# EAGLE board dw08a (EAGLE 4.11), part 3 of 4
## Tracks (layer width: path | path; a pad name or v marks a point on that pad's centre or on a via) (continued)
I_DATA05  (via drill 0.61) (continued)
  Top 0.152: v51.44,4.51 32.51,23.43 30.86,23.43 B22.R2 | v130.18,31.3 131.44,32.58 v131.19,32.83 | v170.81,70.8 170.94,70.8 v175.26,66.48 202.82,38.92 203.07,38.92 226.82,15.18 227.46,15.18 v228.6,14.03 | v261.37,113.98 261.37,114.11 253.49,121.98 252.48,121.98 v241.94,132.52
  Bottom 0.152: v51.44,4.51 96.52,4.51 101.98,9.97 108.84,9.97 v130.18,31.3 | v131.19,32.83 131.83,32.83 146.94,47.94 147.96,47.94 v170.81,70.8 | v228.6,14.03 228.6,14.29 242.44,28.13 242.7,28.13 244.22,29.65 244.22,29.91 248.79,34.48 250.06,34.48 251.71,36.13 B05.L1 | v261.37,113.98 259.84,112.46 259.84,112.2 255.14,107.5 254,107.5 253.24,106.74 253.11,106.74 A05.L1 | v241.94,132.52 241.94,132.4 234.31,124.78 234.31,124.27 224.41,114.36 223.9,114.36 221.11,111.57 217.93,111.57 203.71,97.35 203.71,94.17 186.06,76.52 185.29,76.52 v175.26,66.48
I_DATA06  (via drill 0.61)
  Top 0.152: v263.02,42.48 263.02,46.55 258.19,51.37 v258.06,51.37 258.32,51.75 248.67,61.4 248.67,62.04 238.12,72.58 236.73,72.58 234.82,74.49 v233.04,74.49 | v277.88,73.98 279.02,73.98 279.91,74.87 279.91,77.28 267.21,89.98 267.21,93.15 265.56,94.81 265.3,94.81 263.78,96.33 263.78,96.58 259.21,101.16 257.94,101.16 256.29,102.81 A05.M1 | v101.47,7.81 89.41,7.81 88.01,9.21 78.99,9.21 78.23,9.97 61.47,9.97 17.78,53.66 17.78,54.8 B23.D2 | v126.75,12.26 v120.65,12.26 | v184.15,61.53 187.58,61.53 194.44,54.67 194.44,54.04 v203.58,44.9
  Bottom 0.152: v263.02,42.48 255.91,35.37 255.91,34.1 B05.M1 | v258.06,51.37 258.06,52.51 262.13,56.58 262.89,56.58 266.06,59.75 266.06,60.39 268.48,62.8 268.48,63.69 269.37,64.58 269.37,65.47 v277.88,73.98 | v101.47,7.81 107.82,7.81 112.27,12.26 v120.65,12.26 | v126.75,12.26 134.87,12.26 v184.15,61.53 | v203.58,44.9 205.23,44.9 221.74,61.4 221.74,64.58 223.39,66.23 223.77,66.23 229.62,72.07 230.63,72.07 v233.04,74.49
I_DATA07  (via drill 0.61)
  Top 0.152: v246.89,21.78 246.51,21.78 229.11,39.18 229.11,42.35 227.46,44.01 224.28,44.01 213.23,55.05 213.23,55.56 v211.71,57.09 | v224.66,70.67 224.66,73.22 v222.12,75.75 | v239.14,97.85 239.14,98.49 238.25,99.38 238.25,103.06 230.63,110.68 230.25,110.68 228.6,112.33 228.6,113.09 229.36,113.86 230.12,113.09 230.12,112.2 233.04,109.28 235.2,109.28 239.27,105.22 242.44,105.22 250.32,97.35 250.32,97.09 v251.33,96.08 | v132.84,136.08 138.56,136.08 185.29,89.34 187.2,89.34 187.45,89.09 190.12,89.09 v216.53,62.67
  Bottom 0.152: v246.89,21.78 247.27,22.16 248.67,22.16 253.11,26.61 254.89,26.61 B05.P1 | v211.71,57.09 211.71,57.72 216.66,62.67 | 216.66,62.67 v224.66,70.67 | v222.12,75.75 222.12,80.83 v239.14,97.85 | v251.33,96.08 254.51,96.08 254.89,96.46 A05.P1 | v132.84,136.08 110.62,113.86 93.22,113.86 34.42,55.05 34.42,51.88 32.89,50.35 23.37,50.35 22.61,49.59 18.16,49.59 B23.F2 | 216.66,62.67 v216.53,62.67
I_DATA08  (via drill 0.61)
  Top 0.152: v109.6,5.14 110.87,3.87 109.86,2.86 109.09,2.86 108.33,3.62 105.66,3.62 102.23,7.05 101.09,7.05 100.84,7.3 61.98,7.3 49.78,19.49 45.59,19.49 44.45,20.64 43.43,20.64 21.59,42.48 18.16,42.48 B23.J2 | v148.97,12.51 152.02,12.51 v154.56,9.97 | v206.38,52.77 206.88,52.77 214.88,44.77 | 214.88,44.77 247.78,11.87 v247.9,11.87 | v214.76,44.64 214.88,44.77
  Bottom 0.152: v109.6,5.14 141.6,5.14 v148.97,12.51 | v154.56,9.97 159.64,9.97 171.07,21.4 172.21,21.4 191.64,40.83 194.82,40.83 205.87,51.88 205.87,52.26 v206.38,52.77 | v247.9,11.87 248.41,11.87 253.49,16.95 253.49,18.1 255.27,19.88 B05.S1 | v214.76,44.64 216.41,46.29 216.41,46.55 235.08,65.22 235.08,65.72 235.71,66.36 235.71,67.25 236.6,68.14 236.6,70.04 240.54,73.98 240.66,73.98 247.14,80.45 247.14,80.58 247.65,81.09 247.78,81.09 250.32,83.63 250.32,83.76 251.33,84.77 251.46,84.77 255.27,88.58 255.27,89.72 A05.S1
I_DATA09  (via drill 0.61)
  Top 0.152: v67.44,67.69 v64.01,67.69 | v149.99,136.02 150.37,136.02 151,135.38 151.89,135.38 166.12,121.16 171.83,121.16 v187.71,105.28 | v195.58,111 195.58,110.74 216.92,89.41 217.17,89.41 v218.19,88.39 | v217.17,87.25 217.68,87.25 220.98,83.95 221.36,83.95 v233.43,71.88 | v230.89,67.06 231.65,67.06 241.68,57.02 241.68,56.52 v242.82,55.37 | v230.89,139.06 235.46,134.49 235.46,134.37 235.59,134.37 235.59,134.24 235.71,134.24 235.71,134.11 235.84,134.11 235.84,133.99 235.97,133.99 235.97,133.86 236.09,133.86 238.63,131.32 238.63,131.19 238.76,131.19 238.76,131.06 238.89,131.06 238.89,130.94 239.01,130.94 239.01,130.81 239.14,130.81 239.14,130.68 239.27,130.68 241.81,128.14 241.81,128.02 241.94,128.02 241.94,127.89 242.06,127.89 242.06,127.76 242.19,127.76 242.19,127.64 242.32,127.64 242.32,127.51 242.44,127.51 242.57,127.38 243.08,127.38 244.6,125.86 245.36,125.86 A05.D2 | v223.52,131.95 222.12,131.95 v219.33,134.75
  Bottom 0.152: v64.01,67.69 63.63,67.31 63.63,66.8 34.42,37.59 23.24,37.59 22.61,36.96 18.16,36.96 B23.L2 | v67.44,67.69 67.44,68.07 70.99,71.63 71.37,71.63 75.06,75.31 75.06,76.71 93.09,94.74 96.39,94.74 107.44,105.79 107.44,108.97 108.46,109.98 108.46,110.11 108.58,110.11 108.58,110.24 108.71,110.24 108.71,110.36 108.84,110.36 108.84,110.49 108.97,110.49 108.97,110.62 114.81,110.62 115.19,111 115.7,111 140.72,136.02 v149.99,136.02 | v187.71,105.28 189.87,105.28 v195.58,111 195.58,111.38 218.95,134.75 v219.33,134.75 | v218.19,88.39 218.19,88.27 v217.17,87.25 | v233.43,71.88 233.43,69.6 v230.89,67.06 | v242.82,55.37 245.36,55.37 B05.D2 | v230.89,139.06 230.63,139.06 v223.52,131.95
I_DATA10  (via drill 0.61)
  Top 0.152: v193.29,141.41 196.34,141.41 199.26,138.49 199.26,138.37 202.06,135.57 202.56,135.57 v212.09,126.05 | v229.62,139.13 229.62,139 232.54,136.08 233.3,136.08 242.32,127.06 242.82,127.06 245.62,124.27 246.89,124.27 248.54,122.62 A05.E2 | v238.12,40.07 238.12,39.69 v247.65,30.16 | v225.04,11.62 223.9,11.62 v207.77,27.75 | v183.9,3.87 178.69,3.87 163.96,18.61 160.78,18.61 152.91,26.48 152.91,30.04 150.11,32.83 150.11,34.61 138.43,46.29 138.43,46.8 136.65,48.58 136.65,50.35 136.4,50.61 136.4,52.51 133.22,55.69 133.22,56.2 124.97,64.45 124.97,64.96 v119,70.93
  Bottom 0.152: v193.29,141.41 187.32,136.08 185.29,136.08 158.62,109.41 158.12,109.41 140.97,92.27 140.59,92.27 135.64,87.31 135.38,87.31 v119,70.93 99.69,51.63 99.44,51.63 95.25,47.43 95.25,46.93 66.93,18.61 61.47,18.61 58.29,15.43 45.59,15.43 42.42,12.26 36.07,12.26 34.92,11.11 32.26,13.78 32.26,14.8 33.4,15.94 19.56,29.78 18.16,29.78 B23.N2 | v212.09,126.05 213.36,126.05 213.87,126.56 217.04,126.56 v229.62,139.13 | v238.12,40.07 238.63,40.58 238.63,43.37 247.27,52.01 248.54,52.01 B05.E2 | v247.65,30.16 230.63,13.14 227.71,13.14 227.2,12.64 226.06,12.64 v225.04,11.62 | v183.9,3.87 v207.77,27.75
I_DATA11  (via drill 0.61)
  Top 0.152: v162.94,91.5 162.94,91.38 178.94,75.37 178.94,74.74 191.9,61.78 191.9,61.02 193.55,59.37 193.55,59.12 217.93,34.73 218.69,34.73 v229.11,24.32 | v254.38,118.68 249.68,123.38 249.3,123.38 v247.78,124.9 | v249.81,126.94 249.17,126.94 v239.4,136.72 | v231.39,123.76 v229.62,125.54 | v226.19,117.54 225.68,117.54 225.3,117.92 225.04,117.92 223.39,119.57 223.01,119.57 219.2,123.38 219.2,123.89 214.88,128.21 214.88,128.71 214.25,129.35 212.85,129.35 211.84,130.37 211.2,130.37 209.8,131.76 209.55,131.76 208.41,132.91 206.5,132.91 v205.99,133.41
  Bottom 0.152: v229.11,24.32 231.27,26.48 231.27,29.65 242.44,40.83 242.95,40.83 243.46,41.34 243.46,41.85 245.62,44.01 246.89,44.01 248.54,45.66 B05.H2 | B23.R2 17.78,23.05 17.78,18.86 20.7,15.94 19.56,14.8 19.56,13.78 22.23,11.11 23.37,12.26 33.27,12.26 41.4,4.13 49.91,4.13 51.05,5.27 58.42,5.27 61.98,8.83 76.58,8.83 150.24,82.49 152.53,82.49 152.91,82.87 154.31,82.87 v162.94,91.5 163.32,91.76 174.5,102.93 175.64,102.93 184.53,111.82 184.53,112.46 185.55,113.47 185.55,114.11 202.18,130.75 203.58,130.75 205.99,133.16 v205.99,133.41 | v254.38,118.68 251.97,116.27 249.94,116.27 A05.H2 | v249.81,126.94 v247.78,124.9 | v239.4,136.72 236.22,136.72 231.9,132.4 231.9,131.25 230.5,129.86 229.87,129.86 229.11,129.09 229.11,128.46 228.35,127.7 228.35,126.81 v229.62,125.54 | v231.39,123.76 231.39,121.86 227.46,117.92 226.57,117.92 v226.19,117.54
I_DATAIN  (via drill 0.61)
  Top 0.152: v87.63,22.16 92.08,22.16 v107.95,6.29 | v214,96.33 214,97.6 v213.74,97.85 | v228.22,114.75 228.22,120.46 v225.68,123 | v247.4,136.84 248.92,136.84 259.84,125.92 259.84,122.75 262,120.59 v262.13,120.59 | v255.02,113.6 263.65,104.97 263.65,104.2 262.76,103.31 262.64,103.44 A04.M2 | v263.27,31.94 262.51,32.7 262.38,32.7 B04.M2 | v305.69,82.49 305.69,83.25 305.31,83.63 305.31,87.06 300.36,92.01 300.36,92.52 298.2,94.68 298.2,96.71 297.81,97.09 297.81,97.73 300.86,100.78 279.91,121.73 279.91,124.9 v274.32,130.49
  Bottom 0.152: v87.63,22.16 87.5,22.04 86.11,23.43 81.66,23.43 B18.R2 | v107.95,6.29 131.7,6.29 147.19,21.78 151,21.78 187.96,58.74 187.96,59.37 189.99,61.4 189.99,68.14 190.63,68.77 190.63,71.94 198.25,79.57 198.25,80.07 200.03,81.85 200.03,82.87 207.14,89.98 207.65,89.98 v214,96.33 | v213.74,97.85 214.38,97.85 219.2,102.68 219.46,102.68 219.84,103.06 219.84,103.44 225.3,108.9 225.3,109.41 228.09,112.2 228.09,114.62 v228.22,114.75 | v225.68,123 226.31,123 227.33,124.02 227.58,124.02 227.97,124.4 229.74,124.4 235.97,130.62 236.47,130.62 242.32,136.46 247.01,136.46 v247.4,136.84 | v255.02,113.6 262,120.59 v262.13,120.59 262.51,120.84 272.16,130.49 v274.32,130.49 | v263.27,31.94 263.27,32.58 263.91,33.21 263.91,33.34 264.29,33.72 264.8,33.72 276.86,45.78 276.86,46.67 282.07,51.88 282.07,56.83 288.42,63.18 288.67,63.18 292.99,67.5 292.99,70.93 295.4,73.34 295.4,74.74 304.04,83.38 304.8,83.38 v305.69,82.49
I_EXTA0  (via drill 0.61)
  Top 0.152: v106.05,4.38 101.6,8.83 98.04,8.83 96.9,9.97 93.22,9.97 84.45,18.73 83.44,18.73 82.68,19.49 70.99,19.49 68.58,21.91 68.58,23.05 B19.R2 | v215.14,68.64 218.44,68.64 220.34,70.55 v227.2,63.69 | v234.06,1.46 228.85,1.46 v224.41,5.91 | v214.88,1.46 214.38,0.95 208.53,0.95 202.18,7.3 201.8,7.3 189.23,19.88 188.98,19.88 v173.23,35.62
  Bottom 0.152: v106.05,4.38 141.99,4.38 v173.23,35.62 178.82,41.21 179.32,41.21 201.17,63.06 205.23,63.06 205.99,63.82 207.77,63.82 210.57,66.61 213.11,66.61 v215.14,68.64 | v227.2,63.69 229.74,66.23 232.03,66.23 246,80.2 A05.V2 | v234.06,1.46 241.05,8.45 241.68,8.45 243.59,10.35 244.22,10.35 244.6,10.73 245.36,10.73 B05.V2 | v224.41,5.91 221.62,5.91 218.69,2.98 216.41,2.98 v214.88,1.46
I_EXTA1  (via drill 0.61)
  Top 0.152: v248.28,16.45 247.65,17.08 246.76,17.08 B05.T2 | v262.76,30.29 262.76,30.92 260.86,32.83 260.86,36.01 252.86,44.01 252.48,44.01 v251.59,44.9 | v263.91,68.64 266.57,68.64 270,72.07 269.49,72.58 269.49,74.49 269.24,74.74 269.24,74.99 266.06,78.17 259.71,78.17 v247.65,90.23 247.4,90.61 243.84,94.17 v243.84,94.68 | v95.63,11.75 87.88,19.49 83.69,19.49 73.41,29.78 68.96,29.78 B19.N2 | v172.59,76.01 176.02,76.01 177.8,74.23 178.18,74.23 189.99,62.42 189.99,62.04 v190.75,61.28 | v194.06,63.06 197.61,63.06 v201.42,59.24
  Bottom 0.152: v248.28,16.45 248.92,16.45 v262.76,30.29 | v251.59,44.9 251.59,46.8 256.67,51.88 256.67,53.91 254.51,56.07 256.67,58.23 256.67,61.4 258.32,63.06 258.7,63.06 259.59,63.94 259.59,64.33 v263.91,68.64 | v247.65,90.23 247.65,89.34 246.38,88.08 A05.T2 | v95.63,11.75 99.06,11.75 99.57,12.26 103.89,12.26 157.99,66.36 162.94,66.36 v172.59,76.01 | v190.75,61.28 192.28,61.28 v194.06,63.06 | v201.42,59.24 203.71,59.24 210.69,66.23 213.87,66.23 230.5,82.87 232.03,82.87 v243.84,94.68
I_EXTA2  (via drill 0.61)
  Top 0.152: v253.87,13.65 249.56,17.97 249.56,19.88 B05.S2 | v244.35,3.62 236.09,3.62 227.46,12.26 225.55,12.26 225.43,12.38 224.16,12.38 208.53,28 208.53,28.13 207.65,29.02 207.52,29.02 206.88,29.65 206.88,33.59 v206.76,33.72 | v216.03,44.77 216.03,45.78 v214.25,47.56 | v109.47,3.62 93.6,19.49 90.04,19.49 88.14,21.4 87.25,21.4 76.45,32.19 70.99,32.19 68.58,34.61 68.58,35.75 B19.L2 | v169.42,9.08 172.34,9.08 v175.01,6.41
  Bottom 0.152: v253.87,13.65 253.37,13.65 251.33,11.62 251.33,10.6 v244.35,3.62 | v216.03,44.77 215.39,44.13 215.39,42.35 v206.76,33.72 206.5,33.34 201.29,28.13 197.99,28.13 195.45,25.59 194.82,25.59 189.1,19.88 188.47,19.88 v175.01,6.41 | v214.25,47.56 224.92,58.23 224.92,62.67 225.55,63.31 225.55,65.22 247.14,86.81 247.14,87.95 248.92,89.72 A05.S2 | v109.47,3.62 146.69,3.62 148.21,5.14 165.48,5.14 v169.42,9.08
I_INIT  (via drill 0.61)
  Top 0.152: v275.21,93.53 v292.35,76.39 | B01.V2 296.16,10.73 292.74,10.73 283.34,1.33 279.4,1.33 275.08,5.65 266.7,5.65 264.8,7.56 264.16,7.56 261.62,10.1 260.1,10.1 259.46,10.73 B04.V2 258.44,11.87 256.67,13.65 256.67,14.8 251.59,19.88 251.59,20.77 242.57,29.78 240.41,29.78 B06.N1 239.4,30.92 237.62,32.7 237.62,33.85 232.92,38.54 232.92,39.56 227.84,44.64 v227.84,46.93
  Bottom 0.152: v275.21,93.53 263.02,81.34 259.46,81.34 A04.V2 258.44,80.2 258.44,76.39 257.3,75.25 257.3,74.99 254,71.69 253.62,71.69 251.33,69.41 251.08,69.41 250.82,69.15 250.44,69.15 250.32,69.03 249.94,69.03 v227.84,46.93 | v292.35,76.39 292.48,76.39 296.42,80.33 A01.V2
I_IOP1  (via drill 0.61)
  Top 0.152: v309.88,52.77 309.88,85.53 306.07,89.34 305.94,89.34 305.31,89.98 305.31,91 306.58,92.27 305.44,93.41 304.67,93.41 303.28,92.01 302.13,93.15 302.13,104.33 v300.36,106.11 | v248.03,60.26 247.14,61.15 247.14,62.42 244.86,64.71 243.59,64.71 B06.A1 | v260.6,72.83 260.6,74.23 264.16,77.79 265.3,77.79 v265.68,77.41
  Bottom 0.152: v309.88,52.77 303.4,46.29 303.4,45.78 300.36,42.74 300.36,40.45 B01.K2 | v300.36,106.11 300.36,108.78 A01.K2 299.34,109.16 297.69,107.5 296.29,107.5 266.19,77.41 v265.68,77.41 | v248.03,60.26 v260.6,72.83
I_IOP2  (via drill 0.61)
  Top 0.152: v270.89,85.15 v275.72,80.33 | v294.64,29.53 294.51,29.53 281.31,42.74 280.92,42.74 269.11,54.55 269.11,55.18 v254.89,69.41
  Bottom 0.152: 255.02,69.28 v270.89,85.15 | 255.02,69.28 245.36,59.63 245.11,59.63 243.97,58.48 243.97,58.23 241.68,55.94 240.41,55.94 B06.D1 | v275.72,80.33 275.72,80.45 283.72,88.46 283.97,88.46 285.62,90.11 285.62,90.36 296.42,101.16 297.69,101.16 299.34,102.81 A01.M2 | v294.64,29.53 298.07,32.96 299.34,32.96 B01.M2 | 255.02,69.28 v254.89,69.41
I_IOP4  (via drill 0.61)
  Top 0.152: v264.16,25.97 263.02,27.11 263.02,27.5 241.68,48.83 240.41,48.83 B06.F1 | B01.P2 299.34,27.37 297.94,28.77 294.26,28.77 281.05,41.97 v280.92,41.97 280.67,42.35 268.22,54.8 v268.22,54.93 | v301.12,92.39 300.36,93.15 300.36,96.08 A01.P2
  Bottom 0.152: v264.16,25.97 264.92,25.97 v280.92,41.97 | v301.12,92.39 301.12,89.85 300.99,89.72 300.99,87.82 291.34,78.17 290.7,78.17 271.02,58.48 271.02,57.72 v268.22,54.93
I_IRQ  (via drill 0.61)
  Top 0.152: v274.32,30.35 274.32,32.64 B03.M2 | v243.46,4.45 236.35,4.45 v236.09,4.7 | v229.87,3.43 227.97,3.43 224.66,6.73 221.74,6.73 219.07,9.4 216.66,9.4 216.15,9.91 212.6,9.91 v207.14,15.37 | v195.45,7.11 194.94,7.11 191.77,10.29 191.39,10.29 189.48,12.19 185.17,12.19 181.23,16.13 179.2,16.13 176.78,18.54 173.61,18.54 v173.48,18.67 | v161.04,6.99 146.56,6.99 143.89,9.65 143.76,9.65 143.76,9.78 143.64,9.78 143.64,9.91 143.51,9.91 143.51,10.03 143.38,10.03 143.38,10.16 143.26,10.16 143.26,10.29 140.59,10.29 135.51,15.37 132.33,15.37 131.7,16 130.43,16 122.94,23.5 121.03,23.5 119.63,24.89 109.47,24.89 101.6,32.77 101.09,32.77 85.47,48.39 82.04,48.39 81.66,48.77 B18.F2 | v230.89,142.88 233.17,142.88 235.33,140.72 237.87,140.72 238.25,140.34 239.65,140.34 267.21,112.78 267.21,108.97 272.54,103.63 273.94,103.63 A03.M2 | v215.9,128.4 215.77,128.4 214.5,129.67 213.11,129.67 v204.6,138.18 | v194.18,133.86 191.26,133.86 189.23,135.89 186.94,135.89 v184.28,138.56 | v97.28,87.25 97.28,85.34 v101.6,81.03
  Bottom 0.152: v274.32,30.35 273.81,30.35 265.81,22.35 265.3,22.35 259.33,16.38 254.89,16.38 248.03,9.53 248.03,9.02 v243.46,4.45 | v236.09,4.7 232.28,4.7 231.01,3.43 v229.87,3.43 | v207.14,15.37 203.71,15.37 v195.45,7.11 | v173.48,18.67 172.72,18.67 v161.04,6.99 | v230.89,142.88 229.87,142.88 229.24,142.24 228.6,142.24 220.73,134.37 220.73,133.48 216.41,129.16 216.41,128.91 v215.9,128.4 | v204.6,138.18 202.95,138.18 201.55,136.78 201.55,136.4 199.01,133.86 v194.18,133.86 | v184.28,138.56 166.62,138.56 164.21,136.14 153.54,136.14 135.64,118.24 134.24,118.24 119.89,103.89 118.24,103.89 116.46,102.11 112.14,102.11 v97.28,87.25 | v101.6,81.03 101.6,72.01 99.06,69.47 98.81,69.47 98.55,69.22 98.17,69.22 98.04,69.09 97.79,69.09 97.66,68.96 92.46,68.96 91.69,68.2 91.69,62.1 84.84,55.24 84.84,54.74 83.06,52.96 83.06,51.56 81.41,49.91 B18.F2
I_LINE  (via drill 0.61)
  Top 0.152: v94.49,47.31 99.82,47.31 105.79,41.34 106.3,41.34 131.32,16.32 137.67,16.32 144.02,9.97 147.07,9.97 v149.22,7.81 | v171.45,20.64 172.59,19.49 178.44,19.49 181.99,15.94 187.83,15.94 v200.15,3.62 | v214.12,8.45 214.88,8.45 v220.98,2.35 | v237.49,17.72 237.87,17.72 245.62,9.97 249.94,9.97 252.73,7.18 258.83,7.18 v261.87,4.13 | v288.8,62.42 287.27,63.94 286.77,63.94 271.78,78.93 271.78,80.2 A03.V2 | v283.72,53.28 283.72,53.15 289.05,47.82 289.05,46.67 v297.94,37.78
  Bottom 0.152: v94.49,47.31 84.07,36.89 81.66,36.89 B18.L2 | v149.22,7.81 158.62,7.81 v171.45,20.64 | v200.15,3.62 209.3,3.62 v214.12,8.45 | v220.98,2.35 222.12,2.35 v237.49,17.72 | v261.87,4.13 264.16,4.13 270.76,10.73 B03.V2 272.16,11.49 273.81,13.14 275.08,13.14 297.94,36.01 v297.94,37.78 | v288.8,62.42 288.8,58.36 v283.72,53.28
I_MB00  (via drill 0.61)
  Top 0.152: v241.3,109.54 249.17,101.66 249.17,101.16 252.09,98.23 252.09,97.98 262.25,87.82 263.02,87.82 271.4,79.44 271.4,78.68 288.42,61.66 289.81,61.66 B02.B1 | v253.11,121.09 252.73,121.09 246,127.83 245.24,127.83 243.33,129.73 242.57,129.73 240.41,131.89 A06.B1 | v284.1,133.41 285.37,132.14 289.81,132.14 A02.B1
  Bottom 0.152: A07.H2 224.16,116.65 224.16,117.79 236.09,129.73 237.36,129.73 239.01,131.38 A06.B1 | v241.3,109.54 251.97,120.21 252.22,120.21 v253.11,121.09 256.03,121.09 268.35,133.41 v284.1,133.41
I_MB01  (via drill 0.61)
  Top 0.152: v241.17,122.87 241.17,123.51 240.03,124.65 A06.D1 | 262.64,85.92 261.87,86.68 261.87,87.19 251.84,97.22 251.46,97.22 242.7,105.98 242.19,105.98 v239.9,108.27 | 262.64,85.92 270.89,77.66 271.4,77.66 290.19,58.86 290.19,56.33 B02.D1 | v225.93,96.08 225.93,96.33 224.28,97.98 223.01,97.98 221.36,99.63 A07.N2 | v292.1,115.63 282.07,125.67 284.23,127.83 284.99,127.83 287.02,125.79 289.81,125.79 A02.D1 | 262.64,85.92 v262.51,85.79
  Bottom 0.152: v241.17,122.87 220.98,102.68 220.98,100.78 A07.N2 | v239.9,108.27 238.12,108.27 v225.93,96.08 | v292.1,115.63 291.85,115.63 264.03,87.82 264.03,87.31 v262.51,85.79
I_MB02  (via drill 0.61)
  Top 0.152: v226.19,82.87 225.3,83.76 224.54,83.76 A07.U2 | v235.59,92.27 235.59,93.92 226.44,103.06 226.44,104.2 v213.74,116.9 | v219.96,123.76 221.74,123.76 224.41,126.43 236.09,114.75 239.4,114.75 v239.65,114.49 | v244.73,120.08 244.6,120.08 243.21,121.47 A06.E1 | v238.51,111.06 262.51,87.06 | 262.51,87.06 293.37,56.2 293.37,53.15 B02.E1 | v293.75,119.44 293.75,121.47 A02.E1 | 262.51,87.06 v262.64,87.06
  Bottom 0.152: v226.19,82.87 226.19,83.38 233.17,90.36 233.68,90.36 v235.59,92.27 | v213.74,116.9 215.39,118.56 215.39,120.08 215.77,120.46 216.66,120.46 216.92,120.71 217.55,120.71 218.57,121.73 218.57,122.36 v219.96,123.76 | v244.73,120.08 239.65,115 v239.65,114.49 239.4,114.11 238.51,113.22 v238.51,111.06 | v293.75,119.44 293.75,118.43 291.34,116.01 291.34,115.76 v262.64,87.06
I_MB03  (via drill 0.61)
  Top 0.152: v229.62,117.79 230.89,117.79 236.09,112.58 236.85,112.58 238.12,113.86 239.01,112.97 A06.J1 240.41,112.33 242.06,110.68 243.33,110.68 261.11,92.9 | v291.85,45.53 291.85,46.29 286.26,51.88 286.26,53.15 285.62,53.78 285.62,55.69 284.61,56.71 284.35,56.71 282.32,58.74 282.32,58.99 275.08,66.23 274.83,66.23 273.3,67.75 273.3,70.04 v270.26,73.09 | v273.69,78.3 273.69,80.33 261.11,92.9 | v286.13,117.03 287.78,117.03 289.05,115.76 289.05,115.25 290.19,114.11 290.19,113.47 A02.J1 | 261.11,92.9 v262,92.9
  Bottom 0.152: v229.62,117.79 213.61,101.79 211.46,101.79 210.06,100.39 208.66,100.39 A08.N2 | v291.85,45.53 290.83,44.51 290.83,43.62 B02.J1 | v270.26,73.09 270.26,74.87 v273.69,78.3 | v262,92.9 v286.13,117.03
I_MB03\  (via drill 0.61)
  Top 0.152: v224.41,125.28 225.04,125.28 v236.35,113.98 | 239.9,116.14 242.19,116.14 A06.H1 | v239.01,116.14 239.9,116.14 | v242.7,41.72 248.28,36.13 248.28,35.62 249.43,34.48 249.68,34.48 258.83,25.34 259.33,25.34 280.54,4.13 281.31,4.13 283.46,1.97 302.01,20.51 302.01,29.02 301.12,29.91 301.12,33.85 299.59,35.37 299.59,37.15 299.08,37.66 299.08,38.29 294,43.37 294,45.28 B02.H1 | v246.63,46.93 248.28,48.58 246.51,50.35 246.13,50.35 244.6,51.88 244.6,52.39 242.06,54.93 242.06,55.56 v240.92,56.71 | v244.35,62.17 244.22,62.17 235.71,70.67 235.71,70.8 233.81,72.71 233.17,72.71 221.62,84.26 221.23,84.26 209.93,95.57 208.53,95.57 v202.18,101.92 | v273.18,100.01 273.05,100.01 265.56,107.5 v263.52,107.5 | v257.18,103.19 256.03,104.33 251.71,104.33 239.9,116.14
  Bottom 0.152: 215.26,116.14 211.84,116.14 A08.H2 | 215.26,116.14 v224.41,125.28 | v236.35,113.98 236.85,113.98 v239.01,116.14 | v242.7,41.72 242.7,42.99 v246.63,46.93 | v240.92,56.71 240.92,58.36 242.44,59.88 243.08,59.88 243.59,60.39 243.59,61.4 v244.35,62.17 | v202.18,101.92 202.18,102.17 210.69,110.68 210.95,110.68 211.84,111.57 211.84,112.71 215.26,116.14 | v273.18,100.01 294.39,121.22 295.15,120.46 295.15,119.7 294.77,119.32 294.77,118.94 294,118.17 294,116.65 A02.H1 | v263.52,107.5 261.49,107.5 v257.18,103.19
I_MB04  (via drill 0.61)
  Top 0.152: v230,94.3 229.87,94.3 v206.38,117.79 | v200.79,114.36 200.28,114.36 199.14,115.51 A09.H2 | v264.54,64.83 266.19,63.18 266.32,63.18 293.37,36.13 293.37,34.1 B02.M1 | v287.4,87.82 287.4,87.95 285.37,89.98 | 285.37,89.98 v284.86,90.49 | v242.06,101.28 242.06,100.27 251.46,90.87 252.48,90.87 v257.81,85.53 | v273.18,98.74 274.83,98.74 281.05,92.52 281.05,92.01 282.07,91 282.07,89.72 283.21,88.58 283.97,88.58 285.37,89.98
  Bottom 0.152: v230,94.3 238.51,102.81 242.19,102.81 A06.M1 242.57,102.42 242.57,101.79 v242.06,101.28 | v206.38,117.79 205.61,117.79 204.85,117.03 204.34,117.03 202.06,114.75 201.17,114.75 v200.79,114.36 | v264.54,64.83 264.54,65.47 286.51,87.44 287.02,87.44 v287.4,87.82 | v284.86,90.49 284.86,91.89 289.05,96.08 289.05,96.97 291.59,99.5 291.59,100.65 293.37,102.42 A02.M1 | v257.81,85.53 258.57,85.53 267.97,94.93 269.37,94.93 v273.18,98.74
I_MB04\  (via drill 0.61)
  Top 0.152: v213.11,82.23 211.71,83.63 A08.U2 | v285.12,32.7 284.48,32.7 261.75,55.44 261.75,56.45 v251.33,66.86 | v223.52,92.52 223.52,92.39 228.09,87.82 228.09,87.31 230.12,85.28 230.63,85.28 234.44,81.47 234.44,81.09 v248.79,66.74
  Bottom 0.152: v213.11,82.23 214.5,83.63 214.76,83.63 223.52,92.39 | 223.52,92.39 232.66,101.54 233.17,101.54 235.97,104.33 237.36,104.33 239.01,105.98 A06.L1 | v285.12,32.7 288.54,36.13 289.81,36.13 B02.L1 | A02.L1 289.81,105.98 289.43,105.6 288.54,105.6 287.27,104.33 286.89,104.33 275.97,93.41 275.97,93.15 274.45,91.63 274.19,91.63 257.68,75.12 257.68,74.87 251.33,68.52 v251.33,66.86 250.95,66.74 v248.79,66.74 | 223.52,92.39 v223.52,92.52
I_MB05  (via drill 0.61)
  Top 0.152: v299.59,28.64 299.59,30.42 268.35,61.66 268.35,62.17 v266.57,63.94 258.7,71.82 258.7,72.45 250.95,80.2 250.95,84.01 246.51,88.46 245.24,88.46 243.59,90.11 A06.S1 242.57,91.25 240.79,93.03 240.79,94.17 229.24,105.73 v228.6,105.73 | v203.58,82.61 202.44,83.76 199.14,83.76 A09.U2
  Bottom 0.152: v299.59,28.64 294,23.05 294,21.4 B02.S1 | v203.58,82.61 204.85,81.34 205.61,82.11 205.61,82.74 v228.6,105.73 | v266.57,63.94 267.21,64.58 267.21,65.6 284.61,83 287.78,83 291.59,86.81 291.59,87.06 293.37,88.84 293.37,89.72 A02.S1
I_MB05\  (via drill 0.61)
  Top 0.152: v197.61,98.49 196.47,99.63 195.96,99.63 A09.N2 | v211.07,111.95 211.71,111.95 219.84,103.82 219.84,103.31 v233.55,89.6 | v230.5,86.04 246.89,69.66 247.01,69.66 v257.56,59.12 292.74,23.94 293.24,23.94 293.75,24.45 293.75,26.23 B02.P1
  Bottom 0.152: v197.61,98.49 v211.07,111.95 | A06.P1 242.19,96.46 240.54,94.81 239.27,94.81 234.06,89.6 v233.55,89.6 233.3,89.22 230.5,86.42 v230.5,86.04 | v257.56,59.12 293.37,94.93 293.37,96.08 A02.P1
I_MB06  (via drill 0.61)
  Top 0.152: v199.9,87.82 199.52,88.2 197.61,88.2 190.63,95.19 190.63,95.44 186.44,99.63 183.26,99.63 A10.N2 | v285.37,50.35 285.37,50.48 282.96,52.9 282.96,54.67 v271.78,65.85 | v278.76,74.87 278.76,76.14 266.06,88.84 266.06,89.85 265.94,89.98 265.94,91.25 v257.18,100.01 | v254.38,136.08 256.03,136.08 272.54,119.57 272.54,118.3 v273.3,117.54
  Bottom 0.152: v199.9,87.82 199.9,88.46 201.42,89.98 202.06,89.98 207.26,95.19 207.52,95.19 227.84,115.51 228.22,115.51 229.74,117.03 230,117.03 230.38,117.41 230.38,117.67 232.92,120.21 234.44,120.21 235.97,121.73 A06.E2 237.24,122.62 238.76,122.62 240.54,124.4 241.3,124.4 245.11,128.21 246.51,128.21 v254.38,136.08 | v285.37,50.35 286.77,51.75 286.89,51.75 B02.E2 | v271.78,65.85 271.78,66.99 273.69,68.9 273.94,68.9 278.64,73.6 278.64,74.74 v278.76,74.87 | v257.18,100.01 264.67,107.5 269.62,107.5 273.3,111.19 | 273.3,111.19 277.88,115.76 278.51,115.76 283.97,121.22 286,121.22 286.64,121.86 A02.E2 | v273.3,117.54 273.3,111.19
I_MB06\  (via drill 0.61)
  Top 0.152: v201.29,123.38 v209.93,123.38 | v221.87,129.86 225.17,129.86 227.97,127.06 230.63,127.06 232.66,125.03 A06.D2 233.68,124.65 233.68,121.6 v234.19,121.09 | A10.H2 v188.47,115.89 | v282.96,60.39 v284.86,58.48 | v294.51,79.69 294.51,81.72 288.16,88.08 288.16,88.2 287.02,89.34 286.89,89.34 286.26,89.98 286.26,90.23 285.24,91.25 284.99,91.25 279.91,96.33 279.91,100.52 v269.11,111.32
  Bottom 0.152: v188.47,115.89 190.5,115.89 194.82,120.21 198.12,120.21 v201.29,123.38 | v209.93,123.38 214.12,123.38 214.63,123.89 215.9,123.89 v221.87,129.86 | v284.86,58.48 284.48,58.1 284.48,56.33 B02.D2 | v282.96,60.39 282.96,64.45 285.37,66.86 285.37,67.63 285.75,68.01 285.75,69.28 287.02,70.55 287.02,72.2 v294.51,79.69 | v269.11,111.32 269.11,115 271.78,117.67 272.29,117.67 272.92,118.3 275.46,118.3 280.54,123.38 281.81,123.38 283.46,125.03 A02.D2 284.73,125.92 286.26,127.44 286.26,129.09 287.91,130.75 281.81,136.84 254,136.84 245.75,128.59 244.98,128.59 242.95,126.56 239.27,126.56 234.19,121.47 v234.19,121.09
I_MB07  (via drill 0.61)
  Top 0.152: v270.26,58.1 271.65,56.71 271.91,56.71 287.02,41.59 287.02,40.45 B02.K2 | v290.96,78.93 290.45,78.93 276.35,93.03 276.35,94.3 v275.97,94.68 | v288.67,107.63 288.67,107.76 287.65,108.78 A02.K2 | v177.8,120.21 178.69,120.21 v212.09,86.81 | v264.54,96.71 v270.89,90.36 | v257.3,90.61 257.3,91.25 251.71,96.84 251.33,96.84 242.57,105.6 242.06,105.6 240.16,107.5 238.89,107.5 237.24,109.16 A06.K2
  Bottom 0.152: v270.26,58.1 270.26,58.23 v290.96,78.93 | v288.67,107.63 275.97,94.93 v275.97,94.68 275.59,94.42 274.95,94.42 v270.89,90.36 | v177.8,120.21 175.77,120.21 173.35,117.79 173.35,116.65 A11.H2 | v212.09,86.81 212.09,87.19 220.6,95.69 221.11,95.69 232.92,107.5 234.19,107.5 235.84,109.16 A06.K2 | v264.54,96.71 263.4,96.71 v257.3,90.61
I_MB07\  (via drill 0.61)
  Top 0.152: v187.32,81.09 186.06,82.36 186.06,83.38 A10.U2 | v221.11,114.62 v227.97,107.76 228.22,107.38 251.33,84.26 251.33,84.01 | 251.33,84.01 251.33,80.33 259.08,72.58 259.08,71.94 264.67,66.36 266.06,66.36 267.21,65.22 267.21,64.58 268.99,62.8 269.49,62.8 270.38,61.91 270.38,61.4 282.7,49.09 282.7,48.58 284.86,46.42 286.64,46.42 B02.H2 | 251.33,84.01 v251.71,84.01
  Bottom 0.152: v187.32,81.09 187.32,81.47 217.81,111.95 218.31,111.95 220.98,114.62 v221.11,114.62 | v227.97,107.76 230,107.76 234.44,112.2 234.44,113.35 236.22,115.13 A06.H2 | v251.71,84.01 251.84,84.01 259.97,92.14 262.38,92.14 264.03,93.79 264.03,94.17 285.37,115.51 286.64,115.51 A02.H2
I_MB08  (via drill 0.61)
  Top 0.152: v174.88,82.11 173.48,83.5 A11.U2 | v194.94,102.17 195.71,102.17 208.28,89.6 208.28,88.58 212.22,84.64 212.22,84.39 214.5,82.11 216.41,82.11 v218.31,80.2 | v261.49,50.23 277.62,34.1 277.62,33.59 283.85,27.37 286.64,27.37 B02.P2 | 245.36,58.86 243.97,60.26 243.97,60.77 237.24,67.5 236.73,67.5 v221.11,83.12 | 245.36,58.86 v257.68,46.55 | v282.96,95.31 v285.24,95.31 | 245.36,58.86 v245.49,58.86
  Bottom 0.152: v174.88,82.11 v194.94,102.17 | 221.23,83.12 232.92,94.81 234.19,94.81 235.84,96.46 A06.P2 | v218.31,80.2 221.23,83.12 | v261.49,50.23 261.37,50.23 v257.68,46.55 | 221.23,83.12 v221.11,83.12 | v285.24,95.31 286.38,96.46 286.64,96.46 A02.P2 | v282.96,95.31 282.96,94.68 277.11,88.84 276.61,88.84 271.78,84.01 270.38,84.01 261.49,75.12 261.49,74.87 v245.49,58.86
I_MB08\  (via drill 0.61)
  Top 0.152: v171.7,97.98 170.31,99.38 A11.N2 | v185.67,111.95 186.44,111.95 208.66,89.72 208.66,89.09 v214.88,82.87 | v292.99,24.83 292.86,24.83 287.65,30.04 287.65,32.58 B02.M2 | v277.37,13.14 273.05,13.14 v232.92,53.28 | v244.73,72.96 244.22,72.96 240.28,76.9 240.28,77.53 v225.04,92.77 | v288.93,104.84 288.93,105.73 281.69,112.97 281.69,113.6 279.91,115.38 279.91,118.05 279.65,118.3 279.65,119.7 270.64,128.71 269.75,128.71 v264.54,133.92 | v231.14,106.87 231.27,106.87 232.92,105.22 234.19,105.22 235.84,103.57 A06.M2
  Bottom 0.152: v171.7,97.98 v185.67,111.95 | v214.88,82.87 214.88,83.12 223.39,91.63 223.77,91.63 224.28,92.14 224.28,92.52 224.79,93.03 | 224.79,93.03 232.92,101.16 233.3,101.16 234.7,102.55 235.59,102.55 235.84,102.81 A06.M2 | v292.99,24.83 292.99,24.7 287.78,19.49 283.72,19.49 v277.37,13.14 | v232.92,53.28 232.92,53.53 240.79,61.4 240.79,69.03 v244.73,72.96 | 224.79,93.03 v225.04,92.77 | v288.93,104.84 287.91,103.82 287.91,103.69 A02.M2 | v264.54,133.92 263.14,133.92 262.51,133.29 257.94,133.29 248.28,123.64 247.14,123.64 243.97,120.46 243.97,119.95 238.89,114.87 238.89,114.62 236.73,112.46 236.73,112.08 232.03,107.38 231.65,107.38 v231.14,106.87
I_MB09  (via drill 0.61)
  Top 0.152: v163.32,116.27 163.7,116.27 175.51,104.46 175.64,104.46 179.83,100.27 179.83,100.14 v188.59,91.38 | v211.71,113.73 211.71,113.09 219.96,104.84 220.6,104.84 232.92,92.52 234.19,92.52 235.84,90.87 A06.S2 236.85,89.72 238.63,87.95 238.63,86.81 241.05,84.39 v241.05,77.28 | 259.21,51.37 255.78,54.8 255.78,55.44 238.25,72.96 237.62,72.96 v237.24,73.34 | 259.21,51.37 287.02,23.56 287.02,21.4 B02.S2 | v285.75,88.46 285.75,87.31 v290.07,83 | 259.21,51.37 v259.33,51.37
  Bottom 0.152: v163.32,116.27 161.04,116.27 A12.H2 | v188.59,91.38 189.36,91.38 200.28,102.3 200.41,102.3 210.31,112.2 210.31,112.33 v211.71,113.73 | v237.24,73.34 237.24,73.47 v241.05,77.28 | v285.75,88.46 287.02,89.72 A02.S2 | v290.07,83 290.07,82.11 289.43,81.47 289.43,81.22 286.38,78.17 286.13,78.17 270.38,62.42 270.38,62.17 269.49,61.28 269.24,61.28 v259.33,51.37
I_MB10  (via drill 0.61)
  Top 0.152: B02.T2 284.86,17.84 286.26,17.84 289.69,21.27 289.69,23.05 289.43,23.3 289.43,26.48 262.38,53.53 258.19,53.53 v256.54,55.18 229.11,82.61 v228.98,82.61 228.73,83 214.5,97.22 214.5,98.23 212.47,100.27 211.46,100.27 195.33,116.39 v194.31,116.39 | v165.1,106.36 165.48,106.36 v173.35,98.49 | v285.88,85.15 284.48,86.55 A02.T2
  Bottom 0.152: v228.98,82.61 228.98,84.52 229.74,85.28 231.01,85.28 232.66,86.93 A06.T2 | v165.1,106.36 159.13,100.39 157.86,100.39 A12.N2 | v173.35,98.49 173.35,98.74 178.94,104.33 182.12,104.33 189.99,112.2 189.99,112.58 191.01,113.6 191.52,113.6 v194.31,116.39 | v285.88,85.15 285.88,84.77 266.83,65.72 266.83,65.47 v256.54,55.18
I_MB11  (via drill 0.61)
  Top 0.152: v269.11,62.04 282.32,48.83 282.32,48.45 300.36,30.42 300.36,30.16 301.62,28.89 301.62,26.86 286.26,11.49 284.86,11.49 B02.V2 | v286,78.93 284.61,80.33 A02.V2 | v240.92,73.22 233.81,80.33 A06.V2 | v247.9,80.2 248.79,80.2 249.68,79.31 249.68,78.93 263.02,65.6 263.02,64.71 263.91,63.82 264.8,63.82 266.19,62.42 266.19,62.17 v267.59,60.77 | v178.31,68.26 162.81,83.76 161.04,83.76 A12.U2 | v185.8,75.63 186.06,75.63 v192.79,68.9 | v215.52,85.79 217.42,85.79 220.34,82.87 220.34,82.74 220.98,82.11 221.11,82.11 227.71,75.5 v227.71,75.37
  Bottom 0.152: v286,78.93 v269.11,62.04 268.73,61.78 267.72,60.77 v267.59,60.77 | v240.92,73.22 v247.9,80.2 | v178.31,68.26 178.44,68.26 v185.8,75.63 | v192.79,68.9 200.15,68.9 203.96,72.71 203.96,74.23 v215.52,85.79 | v227.71,75.37 232.79,80.45 A06.V2
I_MBINCR  (via drill 0.61)
  Top 0.152: 235.46,41.21 235.46,42.35 233.81,44.01 233.17,44.01 231.65,45.53 231.65,46.16 230.63,47.18 230.25,47.18 v228.6,48.83 | 235.46,41.21 235.46,39.18 256.79,17.84 258.06,17.84 B04.T2 | v148.59,4.38 143,9.97 131.32,9.97 122.17,19.11 115.32,19.11 114.94,19.49 109.09,19.49 85.34,43.24 82.68,43.24 70.74,55.18 68.96,55.18 B19.D2 | v174.62,9.08 179.96,9.08 v186.06,2.98 | v233.68,41.21 235.46,41.21
  Bottom 0.152: v228.6,48.83 228.6,49.21 231.27,51.88 231.27,53.66 229.36,55.56 234.95,61.15 234.95,61.91 237.62,64.58 237.62,66.99 237.74,67.12 237.74,68.39 239.4,70.04 240.03,70.04 247.52,77.53 248.67,77.53 249.68,78.55 249.68,79.82 255.14,85.28 256.41,85.28 258.06,86.93 A04.T2 | v148.59,4.38 169.93,4.38 v174.62,9.08 | v186.06,2.98 197.1,2.98 201.42,7.3 201.68,7.3 209.8,15.43 209.8,17.21 228.47,35.88 228.47,36.39 231.27,39.18 231.27,39.43 231.78,39.94 232.41,39.94 v233.68,41.21
I_RUN  (via drill 0.61)
  Top 0.152: 239.52,50.99 240.28,50.99 264.92,26.35 264.92,25.72 v271.02,19.62 | v237.49,50.99 239.52,50.99 | v147.19,56.71 153.29,56.71 v158.5,51.5 | v185.55,77.66 185.55,78.42 186.69,79.57 187.45,78.8 187.45,78.17 208.03,57.59 208.03,57.09 209.04,56.07 209.04,54.8 209.42,54.42 210.69,54.42 221.74,43.37 221.74,42.23 223.52,40.45 B07.K2 | v271.4,92.01 272.54,90.87 273.94,90.87 A03.S2 | v232.54,57.09 233.43,57.09 239.52,50.99
  Bottom 0.152: v237.49,50.99 233.68,47.18 229.74,47.18 224.16,41.59 224.16,40.45 B07.K2 | v271.02,19.62 273.3,19.62 273.94,20.26 B03.S2 | v147.19,56.71 136.91,46.42 135.64,46.42 B14.H2 | v158.5,51.5 158.5,52.13 172.59,66.23 173.86,66.23 174.88,67.25 175.13,67.25 v185.55,77.66 | v271.4,92.01 262.38,83 261.62,83 260.99,82.36 255.4,82.36 252.86,79.82 251.46,79.82 248.79,77.15 247.65,77.15 243.97,73.47 243.97,72.71 240.41,69.15 240.41,66.74 235.46,61.78 235.46,61.15 232.66,58.36 232.66,57.21 v232.54,57.09
I_SKIP  (via drill 0.61)
  Top 0.152: v288.93,55.56 288.93,59.63 271.27,77.28 267.46,77.28 266.19,78.55 265.18,78.55 v260.6,83.12 | v268.35,94.17 268.35,95.06 v265.68,97.73 | v79.88,44.07 79.88,42.29 80.39,41.78 84.07,41.78 v109.47,16.38 | v125.86,28.07 131.19,28.07 149.99,9.27 151.76,9.27 v152.27,8.76 | v172.85,24.77 172.97,24.77 v175.01,22.73 | v180.97,24.89 183.13,24.89 193.17,14.86 193.17,11.56 194.69,10.03 196.09,10.03 199.9,6.22 201.04,6.22 201.55,5.71 202.69,5.71 v203.96,4.45 | v210.57,5.97 211.84,5.97 v213.49,4.32 | v217.3,7.24 218.95,7.24 v223.52,2.67 | v231.01,9.91 231.78,9.91 235.08,6.6 237.49,6.6 v238.89,5.21 | v266.57,2.79 v268.61,4.83 | v303.4,39.88 303.4,40.13 v295.78,47.75 | v297.56,53.21 295.78,54.99 295.78,58.17 294.77,59.18 294.77,59.31 294.64,59.31 294.64,59.44 294.51,59.44 294.51,59.56 294.39,59.56 294.39,59.69 294.26,59.69 294.26,59.82 v291.08,59.82
  Bottom 0.152: v260.6,83.12 260.6,86.42 v268.35,94.17 | v265.68,97.73 266.32,97.73 270,101.41 270,103.31 272.54,105.86 272.54,107 274.32,108.78 A03.K2 | B03.K2 274.95,40.45 274.95,41.59 283.72,50.35 284.23,50.35 286.13,52.26 286.13,52.77 v288.93,55.56 289.18,56.01 291.08,57.91 v291.08,59.82 | v79.88,44.07 79.88,49.78 80.52,50.42 80.52,54.86 B18.D2 | v109.47,16.38 114.17,16.38 v125.86,28.07 | v152.27,8.76 154.31,10.79 155.19,10.79 159.77,15.37 163.45,15.37 v172.85,24.77 | v175.01,22.73 178.82,22.73 v180.97,24.89 | v203.96,4.45 209.04,4.45 v210.57,5.97 | v213.49,4.32 214.38,4.32 v217.3,7.24 | v223.52,2.67 225.3,2.67 229.62,6.99 229.62,8.51 v231.01,9.91 | v238.89,5.21 238.89,2.29 240.28,0.89 264.67,0.89 v266.57,2.79 | v268.61,4.83 268.61,5.46 277.11,13.97 277.62,13.97 283.46,19.81 283.97,19.81 286,21.84 286,22.48 v303.4,39.88 | v295.78,47.75 295.78,50.04 297.18,51.44 297.18,52.83 v297.56,53.21
I_TS1  (via drill 0.61)
  Top 0.152: v249.81,42.61 v253.37,39.05 262,30.42 262,29.78 279.02,12.76 279.65,12.76 283.85,8.57 292.35,17.08 296.16,17.08 B01.T2
  Bottom 0.152: v249.81,42.61 247.4,42.61 243.33,38.54 242.06,38.54 240.41,36.89 B06.L1 | v253.37,39.05 267.84,53.53 267.97,53.53 269.11,54.67 269.11,55.31 272.54,58.74 272.54,59.5 290.83,77.79 291.46,77.79 303.66,89.98 303.66,90.61 304.29,91.25 304.29,93.03 304.93,93.66 303.78,94.81 302.77,94.81 301.12,93.15 300.74,93.15 297.18,89.6 297.18,88.08 A01.T2
I_TS3  (via drill 0.61)
  Top 0.152: 249.05,36.64 272.92,12.76 276.61,12.76 276.99,12.38 279.53,12.38 283.72,8.19 289.18,8.19 300.36,19.37 299.85,19.88 B01.S2 | 249.05,36.64 243.21,42.48 240.41,42.48 B06.J1 | 249.05,36.64 v249.05,36.01
  Bottom 0.152: v249.05,36.01 253.87,40.83 254.38,40.83 267.46,53.91 267.46,55.31 269.49,57.34 269.49,58.48 269.88,58.86 270,58.86 290.19,79.06 290.19,79.31 290.7,79.82 290.96,79.82 299.72,88.58 299.72,89.72 A01.S2
I_TT_INST  (via drill 0.61)
  Top 0.152: v139.7,34.48 143.89,34.48 v160.78,17.59 | v201.29,52.51 201.29,52.13 218.19,35.24 221.62,35.24 223.14,33.72 B07.M2 | v259.46,8.19 252.73,8.19 v239.78,21.14 v225.93,34.99 | v284.86,70.67 284.48,71.06 284.48,71.94 281.43,74.99 281.43,75.63 280.29,76.77 280.29,77.41 278.89,78.8 278.89,81.47 274.57,85.79 274.07,85.79 272.92,86.93 272.16,86.93 A03.T2 | v271.53,53.28 v269.88,54.93
  Bottom 0.152: v139.7,34.48 135.76,30.54 132.46,30.54 B14.N2 | v160.78,17.59 160.78,18.1 189.99,47.31 191.26,47.31 194.69,50.74 199.52,50.74 v201.29,52.51 | v259.46,8.19 268.35,17.08 270.76,17.08 B03.T2 | v225.93,34.99 225.81,34.99 224.54,33.72 B07.M2 | v284.86,70.67 284.23,70.67 278.13,64.58 278.13,64.33 273.18,59.37 273.18,58.86 270.38,56.07 270.38,55.44 v269.88,54.93 | v271.53,53.28 271.53,52.9 v239.78,21.14
I_WCOV  (via drill 0.61)
  Top 0.152: v170.31,2.35 165.86,6.79 163.58,6.79 161.54,8.83 154.05,8.83 153.29,9.59 150.24,9.59 130.81,29.02 124.97,29.02 124.21,29.78 119.76,29.78 B15.N2 | v184.15,10.48 187.96,10.48 188.47,9.97 191.52,9.97 195.45,6.03 196.47,6.03 v198.88,3.62 | v217.42,22.29 218.57,21.14 218.57,20 220.34,18.22 B07.T2 221.36,17.08 223.01,15.43 224.28,15.43 226.31,13.4 v226.82,13.4 | v243.46,30.04 v247.52,25.97 | v250.82,94.81 249.56,96.08 A05.P2 | v203.2,39.69 207.52,35.37 210.69,35.37 218.57,27.5 218.57,25.08 v218.69,24.96
  Bottom 0.152: v170.31,2.35 174.24,2.35 174.5,2.6 175.13,2.6 176.66,4.13 177.8,4.13 v184.15,10.48 | v198.88,3.62 199.01,3.62 199.77,4.38 202.82,4.38 209.04,10.6 209.04,13.91 v217.42,22.29 217.68,22.67 218.69,23.69 v218.69,24.96 | v247.52,25.97 248.16,26.61 248.54,26.61 B05.P2 | v243.46,30.04 v226.82,13.4 | v250.82,94.81 250.82,94.55 246.89,90.61 246.89,90.23 221.36,64.71 221.36,64.2 200.53,43.37 200.53,40.2 198.88,38.54 198.5,38.54 197.99,38.04 197.99,37.27 199.39,35.88 v203.2,39.69
N$1  (via drill 0.61)
  Top 0.152: v213.49,44.51 212.34,45.66 211.84,45.66 B08.H2 | v231.78,63.06 234.57,63.06 v236.22,61.4
  Bottom 0.152: v213.49,44.51 225.93,56.96 225.93,57.21 v231.78,63.06 | v236.22,61.4 238.89,61.4 239.01,61.53 B06.B1
N$2  (via drill 0.61)
  Top 0.152: v212.22,28.64 211.07,29.78 208.66,29.78 B08.N2
  Bottom 0.152: v212.22,28.64 217.04,28.64 232.79,44.39 233.3,44.39 239.27,50.35 240.54,50.35 242.19,52.01 B06.E1
N$3
  Bottom 0.152: B08.U2 211.84,14.67 213.87,14.67 238.89,39.69 238.89,40.32 240.79,42.23 240.79,43.5 242.57,45.28 B06.H1
N$4  (via drill 0.61)
  Top 0.152: v224.79,24.45 214.5,34.73 212.47,34.73 208.91,38.29 207.39,38.29 205.87,39.81 205.87,40.2 200.41,45.66 199.14,45.66 B09.H2 | v241.3,40.83 241.43,40.83 242.19,40.07 B06.K1
  Bottom 0.152: v224.79,24.45 224.92,24.45 v241.3,40.83
N$5  (via drill 0.61)
  Top 0.152: v212.85,16.32 199.39,29.78 195.96,29.78 B09.N2 | v235.33,37.27 236.22,37.27 v241.05,32.45
  Bottom 0.152: v212.85,16.32 214.76,16.32 234.44,36.01 234.44,36.39 v235.33,37.27 | v241.05,32.45 241.68,32.45 242.19,32.96 B06.M1
N$6  (via drill 0.61)
  Top 0.152: v215.01,2.73 213.61,1.33 212.85,1.33 207.77,6.41 206.63,6.41 202.69,10.35 202.69,11.62 200.41,13.91 199.14,13.91 B09.U2 | v240.92,28.64 242.19,27.37 B06.P1
  Bottom 0.152: v240.92,28.64 v215.01,2.73
O_3CYCLE
  Top 0.152: B19.H2 70.74,46.42 69.47,46.42 67.18,48.7 67.18,54.55 66.8,54.93 66.8,57.85 66.55,58.1 66.55,59.5 45.47,80.58 45.47,82.11 44.2,83.38 44.2,83.88 41.4,86.68 41.4,93.03 35.05,99.38 35.05,99.89 32.26,102.68 32.26,108.01 33.02,108.78 A22.K2
O_AC00
  Top 0.152: B16.E2 109.22,53.15 109.22,53.66 108.08,54.8 108.08,55.56 90.68,72.96 90.68,80.83 81.66,89.85 81.66,90.36 72.77,99.25 72.77,99.76 69.98,102.55 69.98,116.78 85.34,132.14 90.04,127.44 91.31,127.44 92.96,125.79 A17.D2
O_AC01  (via drill 0.61)
  Top 0.152: v66.67,91.63 95.76,62.55 95.76,58.23 103.63,50.35 106.81,50.35 109.22,47.94 109.22,46.8 B16.H2
  Bottom 0.152: v66.67,91.63 66.67,93.66 93.22,120.21 94.49,120.21 96.14,121.86 A17.E2
O_AC02  (via drill 0.61)
  Top 0.152: v138.68,67.25 138.68,71.31 132.72,77.28 132.72,77.53 120.52,89.72 120.52,90.61 98.93,112.2 98.93,113.35 97.16,115.13 A17.H2
  Bottom 0.152: v138.68,67.25 111.51,40.07 110.24,40.07 B16.K2
O_AC03  (via drill 0.61)
  Top 0.152: v125.73,51.63 125.73,52.39 112.27,65.85 112.27,66.23 111.51,66.99 111.51,68.01 108.71,70.8 108.71,71.06 108.46,71.31 108.46,71.69 108.33,71.82 108.33,72.45 108.2,72.58 108.2,82.87 98.17,92.9 98.17,93.41 95.38,96.2 95.38,101.92 v94.11,103.19
  Bottom 0.152: v125.73,51.63 109.86,35.75 109.86,34.1 B16.M2 | v94.11,103.19 94.11,105.22 94.74,105.86 94.74,107 96.52,108.78 A17.K2
O_AC04  (via drill 0.61)
  Top 0.152: v68.07,71.69 83.06,56.71 83.06,51.88 107.57,27.37 108.84,27.37 B16.P2
  Bottom 0.152: v68.07,71.69 68.07,72.33 85.6,89.85 85.6,90.36 94.74,99.5 94.74,100.65 96.52,102.42 A17.M2
O_AC05  (via drill 0.61)
  Top 0.152: v137.54,51.12 137.54,52.39 133.99,55.94 133.99,57.09 126.49,64.58 126.49,65.6 98.93,93.15 98.93,94.3 97.16,96.08 A17.P2
  Bottom 0.152: v137.54,51.12 109.86,23.43 109.86,21.4 B16.S2
O_AC06  (via drill 0.61)
  Top 0.152: v78.87,72.07 89.79,61.15 90.17,61.15 96.52,54.8 96.52,53.15 B17.E2
  Bottom 0.152: v78.87,72.07 78.87,72.71 84.2,78.04 84.2,79.44 93.22,88.46 94.49,88.46 96.14,90.11 A17.S2
O_AC07  (via drill 0.61)
  Top 0.152: v99.82,50.86 99.82,52.51 v81.15,71.18 | v94.36,85.28 94.36,86.17 93.98,86.55 A17.T2
  Bottom 0.152: v99.82,50.86 97.16,48.2 97.16,46.8 B17.H2 | v81.15,71.18 81.15,72.07 v94.36,85.28
O_AC08  (via drill 0.61)
  Top 0.152: v80.9,65.6 96.27,50.23 93.73,47.69 93.73,46.93 96.52,44.13 96.52,40.45 B17.K2
  Bottom 0.152: v80.9,65.6 80.9,67.75 93.34,80.2 A17.V2
O_AC09  (via drill 0.61)
  Top 0.152: v124.71,69.91 124.71,73.72 105.28,93.15 105.28,99.5 83.06,121.73 83.06,122.87 81.28,124.65 A18.D2
  Bottom 0.152: v124.71,69.91 97.92,43.12 97.92,39.18 97.16,38.42 97.16,34.1 B17.M2
O_AC10  (via drill 0.61)
  Top 0.152: v134.75,56.33 134.75,56.83 126.87,64.71 126.87,65.98 117.47,75.37 117.47,78.55 117.09,78.93 117.09,80.83 104.9,93.03 104.9,99.38 82.68,121.6 82.68,122.11 79.88,124.9 79.88,126.05 80.9,127.06 82.04,125.92 82.04,124.78 83.82,123 A18.E2
  Bottom 0.152: v134.75,56.33 133.6,55.18 133.6,54.8 110.11,31.3 105.92,31.3 101.98,27.37 97.54,27.37 B17.P2
O_AC11  (via drill 0.61)
  Top 0.152: v129.03,48.32 129.03,49.59 112.65,65.98 112.65,66.36 111.89,67.12 111.89,68.14 109.09,70.93 109.09,71.18 108.84,71.44 108.84,71.82 108.71,71.94 108.71,72.58 108.58,72.71 108.58,83 98.55,93.03 98.55,93.53 95.76,96.33 95.76,102.68 86.23,112.2 86.23,113.35 84.45,115.13 A18.H2
  Bottom 0.152: v129.03,48.32 118.75,38.04 118.49,38.04 117.09,36.64 116.71,36.64 101.09,21.02 97.54,21.02 B17.S2
O_ACCEPT  (via drill 0.61)
  Top 0.152: v105.92,47.56 63.37,90.11 59.44,90.11 A20.S2
  Bottom 0.152: v105.92,47.56 109.47,47.56 115.44,53.53 116.71,53.53 118.36,55.18 B15.D2
O_ACCLR  (via drill 0.61)
  Top 0.152: v107.95,61.91 107.95,64.07 104.9,67.12 104.9,68.52 102.36,71.06 102.36,73.22 98.93,76.64 98.68,76.64 98.42,76.9 98.04,76.9 97.92,77.03 97.28,77.03 97.16,77.15 95.89,77.15 83.06,89.98 83.06,95.31 83.82,96.08 A18.P2
  Bottom 0.152: v107.95,61.91 86.11,40.07 84.84,40.07 B18.K2
O_ADD00  (via drill 0.61)
  Top 0.152: v83.44,78.42 83.44,83.25 83.06,83.63 83.06,86.93 71.75,98.23 71.75,99.38 70.61,100.52 70.61,101.41 69.6,102.42 69.6,109.28 66.8,112.08 66.8,123.51 67.94,124.65 A19.D2
  Bottom 0.152: v83.44,78.42 71.25,66.23 70.99,66.23 59.05,54.29 59.05,53.15 B20.E2
O_ADD01  (via drill 0.61)
  Top 0.152: v65.79,55.56 65.79,56.45 57.66,64.58 57.66,64.96 53.47,69.15 53.47,71.44 v51.31,73.6
  Bottom 0.152: v65.79,55.56 59.05,48.83 59.05,46.8 B20.H2 | v51.31,73.6 51.31,87.31 69.72,105.73 69.72,112.58 72.52,115.38 72.52,120.71 71.75,121.47 A19.E2
O_ADD02  (via drill 0.61)
  Top 0.152: v41.91,64.58 53.72,52.77 53.72,48.45 59.94,42.23 59.05,41.34 59.05,40.45 B20.K2
  Bottom 0.152: v41.91,64.58 41.91,75.25 47.37,80.71 47.37,83.88 69.34,105.86 69.34,113.35 71.12,115.13 A19.H2
O_ADD03  (via drill 0.61)
  Top 0.152: v91.44,73.34 91.44,80.58 82.04,89.98 82.04,90.49 73.15,99.38 73.15,99.89 70.36,102.68 70.36,108.01 71.12,108.78 A19.K2
  Bottom 0.152: v91.44,73.34 91.82,72.96 91.82,70.29 89.28,67.75 89.28,66.36 75.69,52.77 75.69,51.88 59.05,35.24 59.05,34.1 B20.M2
O_ADD04  (via drill 0.61)
  Top 0.152: v92.33,74.23 92.33,80.2 82.68,89.85 82.68,90.36 73.53,99.5 73.53,100.65 71.75,102.42 A19.M2
  Bottom 0.152: v92.33,74.23 92.2,74.11 92.2,70.17 89.66,67.63 89.66,66.23 78.87,55.44 78.87,51.88 71.5,44.51 71.5,43.62 59.05,31.18 59.05,27.75 B20.P2
O_ADD05  (via drill 0.61)
  Top 0.152: v41.78,40.2 41.78,36.01 42.8,34.99 42.8,34.48 56.26,21.02 58.04,21.02 B20.S2 | v82.55,80.96 82.55,84.14 73.53,93.15 73.53,94.3 71.75,96.08 A19.P2
  Bottom 0.152: v41.78,40.2 v82.55,80.96
O_ADD06
  Bottom 0.152: B21.E2 46.35,53.15 46.35,56.07 53.21,62.93 53.21,64.33 53.47,64.58 53.47,67.63 54.99,69.15 54.99,72.45 69.34,86.81 69.34,87.95 71.12,89.72 A19.S2
O_ADD07  (via drill 0.61)
  Top 0.152: v74.3,75.63 74.3,77.92 v66.8,85.41
  Bottom 0.152: v74.3,75.63 64.9,66.23 64.64,66.23 46.35,47.94 46.35,46.8 B21.H2 | v66.8,85.41 67.94,86.55 A19.T2
O_ADD08  (via drill 0.61)
  Top 0.152: v75.95,72.07 75.95,72.83 68.58,80.2 A19.V2
  Bottom 0.152: v75.95,72.07 46.35,42.48 46.35,40.45 B21.K2
O_ADD09  (via drill 0.61)
  Top 0.152: v21.59,80.45 35.05,66.99 35.05,61.28 40.13,56.2 38.35,54.42 36.07,54.42 31.75,58.74 29.08,56.07 29.08,55.05 45.72,38.42 45.72,34.1 B21.M2
  Bottom 0.152: v21.59,80.45 21.59,83.5 21.72,83.63 21.72,89.47 44.32,112.08 44.32,112.58 53.47,121.73 53.47,122.87 55.24,124.65 A20.D2
O_ADD10  (via drill 0.61)
  Top 0.152: v22.1,60.26 41.02,41.34 41.02,39.81 41.4,39.43 41.4,35.88 42.42,34.86 42.42,34.35 45.72,31.05 45.72,27.75 B21.P2
  Bottom 0.152: v22.1,60.26 22.1,61.78 23.11,62.8 23.11,77.15 26.04,80.07 26.04,80.58 44.7,99.25 44.7,99.76 57.02,112.08 57.02,112.58 59.82,115.38 59.82,120.71 59.05,121.47 A20.E2
O_ADD11  (via drill 0.61)
  Top 0.152: v16.38,53.91 29.08,41.21 29.08,36.01 30.1,34.99 30.1,34.48 43.56,21.02 45.34,21.02 B21.S2
  Bottom 0.152: v16.38,53.91 16.38,70.93 25.65,80.2 25.65,80.71 44.32,99.38 44.32,99.89 56.64,112.2 56.64,113.35 58.42,115.13 A20.H2
O_BAC00  (via drill 0.61)
  Top 0.152: v189.48,70.8 184.78,75.5 184.78,79.18 184.4,79.57 184.4,83.38 175.13,92.65 175.13,93.41 172.85,95.69 172.59,95.69 144.78,123.51 144.78,124.65 A13.D2
  Bottom 0.152: v189.48,70.8 189.48,70.42 184.66,65.6 184.66,62.29 186.18,60.77 184.66,59.24 184.66,58.1 182.88,56.33 B10.D2
O_BAC01  (via drill 0.61)
  Top 0.152: v152.4,123.38 154.94,123.38 171.32,107 171.32,106.49 187.83,89.98 v187.83,89.85 | v171.96,68.64 174.88,65.72 175.39,65.72 186.56,54.55 186.56,53.15 189.99,49.72 189.99,46.67 v190.5,46.16
  Bottom 0.152: v152.4,123.38 151.64,122.62 148.34,122.62 A13.E2 | v187.83,89.85 187.83,87.82 181.48,81.47 181.48,78.17 v171.96,68.64 | v190.5,46.16 190.5,46.04 187.83,43.37 187.83,42.23 186.06,40.45 B10.K2
O_BAC02  (via drill 0.61)
  Top 0.152: v147.57,111.44 148.08,111.44 169.04,90.49 169.04,89.72 170.94,87.82 170.94,83.88 v188.34,66.48 | v165.48,37.4 167.64,35.24 169.54,35.24 182.12,22.67 183.39,22.67 185.04,21.02 B10.S2
  Bottom 0.152: v147.57,111.44 147.57,115.13 A13.H2 | v188.34,66.48 188.34,62.93 187.83,62.42 187.83,59.75 187.58,59.5 187.58,58.99 167.13,38.54 166.62,38.54 v165.48,37.4
O_BAC03  (via drill 0.61)
  Top 0.152: v135.51,93.41 170.94,57.98 170.94,57.85 172.97,55.82 172.97,53.91 172.09,53.02 170.18,54.93 B11.D2
  Bottom 0.152: v135.51,93.41 147.32,105.22 147.32,108.78 A13.K2
O_BAC04  (via drill 0.61)
  Top 0.152: v180.21,49.72 179.58,49.72 171.32,57.98 171.32,58.36 138.94,90.74 138.94,91.5 v138.56,91.89
  Bottom 0.152: v180.21,49.72 175.01,44.51 175.01,42.99 173.35,41.34 173.35,40.45 B11.K2 | v138.56,91.89 138.56,92.52 145.54,99.5 145.54,100.65 147.32,102.42 A13.M2
O_BAC05  (via drill 0.61)
  Top 0.152: v150.24,51.37 165.61,36.01 165.61,30.92 172.72,23.81 172.72,21.4 B11.S2 | v155.07,57.47 155.07,59.24 148.08,66.23 147.57,66.23 137.29,76.52 137.29,80.2 137.03,80.45 v137.03,84.64
  Bottom 0.152: v150.24,51.37 150.24,52.64 v155.07,57.47 | v137.03,84.64 145.54,93.15 145.54,94.3 147.32,96.08 A13.P2
O_BAC06  (via drill 0.61)
  Top 0.152: v139.45,75.5 156.84,58.1 156.84,56.33 B12.D2 | v148.97,87.95 148.97,88.71 147.96,89.72 A13.S2
  Bottom 0.152: v139.45,75.5 139.45,78.42 v148.97,87.95
O_BAC07  (via drill 0.61)
  Top 0.152: v158.62,41.85 160.02,40.45 B12.K2 | v172.21,55.44 172.21,55.56 v142.75,85.03
  Bottom 0.152: v158.62,41.85 v172.21,55.44 | v142.75,85.03 142.75,85.15 144.15,86.55 A13.T2
O_BAC08  (via drill 0.61)
  Top 0.152: v151.26,33.34 160.02,24.57 160.02,21.4 B12.S2 | v172.09,54.17 172.09,54.42 171.45,55.05 171.45,55.82 153.54,73.72 153.16,73.72 148.21,78.68 147.07,78.68 145.16,80.58 A13.V2
  Bottom 0.152: v151.26,33.34 v172.09,54.17
O_BAC09  (via drill 0.61)
  Top 0.152: v123.7,77.41 127.89,73.22 127.89,70.93 133.86,64.96 133.86,64.58 141.73,56.71 142.24,56.71 143,55.94 143.76,55.94 B13.D2 | v145.54,105.09 145.54,108.14 139.7,113.98 139.7,115.89 133.86,121.73 133.86,122.87 132.08,124.65 A14.D2
  Bottom 0.152: v123.7,77.41 123.7,83.5 132.21,92.01 132.46,92.01 v145.54,105.09
O_BAC10  (via drill 0.61)
  Top 0.152: v119.63,104.71 119.63,101.03 120.14,100.52 120.14,95.69 v132.84,83 | v128.02,74.61 128.02,73.6 145.54,56.07 145.54,53.91 140.21,48.58 141.6,47.18 141.73,47.18 145.54,43.37 145.54,42.23 147.32,40.45 B13.K2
